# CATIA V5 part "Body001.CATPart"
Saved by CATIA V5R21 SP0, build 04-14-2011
Part number: Body001
Definition: design
Nomenclature: Body001
Source: Unknown
Bounding box of the stored display mesh (mm): x -7.5 to 7.5, y -8.826 to 8, z 0 to 0.1
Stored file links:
  C:\Users\beatr\OneDrive\Documents\UNB\2026_1\Pi1\Componentes eletronicos\Encoder\Body001.CATPart
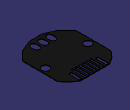
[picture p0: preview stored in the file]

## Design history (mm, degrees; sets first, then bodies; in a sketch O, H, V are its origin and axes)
Body1 "MANIFOLD_SOLID_BREP #388" (main body)
  Solid1: solid without history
